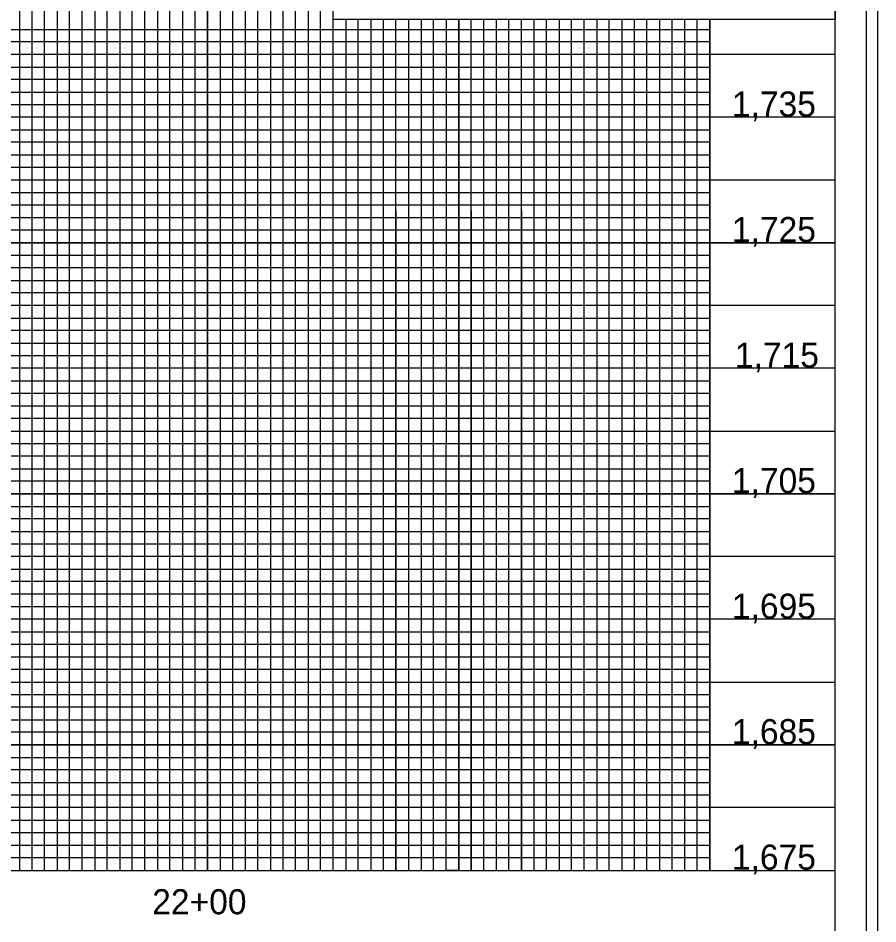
# Model space of a CAD drawing. Extents: x 505692 to 507376, y 438761 to 439861.
# Drawn here: x 507033.2 to 507375.7, y 439314.8 to 439675.6 of the extents above; entities that cross this region are included whole.
import ezdxf

# ---------------------------------------------------------------- set-up
doc = ezdxf.new("R2010")
doc.units = 0
for name, color, linetype in [('Exist Vertical Profile Vertical Axis Label', 7, 'Continuous'), ('Sheet DOT Grid CELL', 7, 'Continuous'), ('Sheet Layout Profile Border Port 1', 7, 'Continuous'), ('Sheet Plot Border Inside CELL', 7, 'Continuous'), ('Sheet Plot Border Outside CELL', 7, 'Continuous'), ('Sheet Profile CELL', 7, 'Continuous'), ('Sheet Profile Grid Major CELL', 7, 'Continuous'), ('Sheet Profile Grid Middle CELL', 7, 'Continuous'), ('Sheet Profile Grid Minor CELL', 7, 'Continuous'), ('Sheet Sticker Exception Certification CELL', 7, 'Continuous')]:
    doc.layers.add(name, color=color, linetype=linetype)

msp = doc.modelspace()

# ---------------------------------------------------------------- linework, layer by layer
at = {"layer": 'Sheet DOT Grid CELL'}
for p, q in [((507058.68, 439336.14), (507058.68, 439836.14)), ((507108.68, 439336.14), (507108.68, 439836.14)), ((507158.68, 439336.14), (507158.68, 439698.59)), ((507208.68, 439336.14), (507208.68, 439675.09)), ((507258.68, 439336.14), (507258.68, 439675.09)), ((507308.68, 439336.14), (507308.68, 439675.09)), ((507358.68, 439636.14), (505858.68, 439636.14)), ((507358.68, 439586.14), (505858.68, 439586.14)), ((507358.68, 439536.14), (505858.68, 439536.14)), ((507358.68, 439486.14), (505858.68, 439486.14)), ((507358.68, 439436.14), (505858.68, 439436.14)), ((507358.68, 439386.14), (505858.68, 439386.14))]:
    msp.add_line(p, q, dxfattribs=at)
at = {"layer": 'Sheet Layout Profile Border Port 1'}
msp.add_lwpolyline([(505908.68, 439836.14), (505908.68, 439336.14), (507108.68, 439336.14), (507108.68, 439486.14), (507108.68, 439636.14), (507108.68, 439836.14)], close=True, dxfattribs=at)
at = {"layer": 'Sheet Plot Border Inside CELL'}
msp.add_lwpolyline([(505704.68, 438783.59), (507371.18, 438783.59), (507371.18, 439838.69), (505704.68, 439838.69)], close=True, dxfattribs=at)
at = {"layer": 'Sheet Plot Border Outside CELL'}
msp.add_lwpolyline([(505691.68, 438761.14), (507375.68, 438761.14), (507375.68, 439861.14), (505691.68, 439861.14)], close=True, dxfattribs=at)
at = {"layer": 'Sheet Profile CELL'}
msp.add_line((505858.68, 439336.14), (507358.68, 439336.14), dxfattribs=at)
msp.add_lwpolyline([(507358.68, 439836.14), (505858.68, 439836.14), (505858.68, 438786.14), (507358.68, 438786.14)], close=True, dxfattribs=at)
at = {"layer": 'Sheet Profile Grid Major CELL'}
for points in [[(507008.68, 439336.14), (507058.68, 439336.14), (507058.68, 439836.14), (507108.68, 439836.14), (507108.68, 439336.14), (507158.68, 439336.14), (507158.68, 439836.14), (507184.98, 439836.14)], [(507308.68, 439675.09), (507308.68, 439336.14), (507358.68, 439336.14), (507358.68, 439686.14)], [(507208.68, 439675.09), (507208.68, 439336.14), (507258.68, 439336.14), (507258.68, 439336.14), (507258.68, 439675.09)], [(507358.68, 439636.14), (505858.68, 439636.14), (505858.68, 439586.14), (507358.68, 439586.14)], [(507358.68, 439536.14), (505858.68, 439536.14), (505858.68, 439486.14), (507358.68, 439486.14)], [(507358.68, 439436.14), (505858.68, 439436.14), (505858.68, 439436.14), (505858.68, 439386.14), (507358.68, 439386.14)]]:
    msp.add_lwpolyline(points, dxfattribs=at)
at = {"layer": 'Sheet Profile Grid Middle CELL'}
for points in [[(506983.68, 439836.14), (507033.68, 439836.14), (507033.68, 439336.14), (507083.68, 439336.14), (507083.68, 439836.14), (507133.68, 439836.14), (507133.68, 439336.14), (507183.68, 439336.14), (507183.68, 439675.09)], [(507183.68, 439598.94), (507183.68, 439336.14), (507233.68, 439336.14), (507233.68, 439675.09)], [(507233.68, 439598.94), (507233.68, 439336.14), (507283.68, 439336.14), (507283.68, 439675.09)], [(507358.68, 439661.14), (505858.68, 439661.14), (505858.68, 439611.14), (507183.68, 439611.14)], [(507183.68, 439611.14), (507358.68, 439611.14)], [(507358.68, 439561.14), (505858.68, 439561.14), (505858.68, 439511.14), (507358.68, 439511.14)], [(507358.68, 439461.14), (505858.68, 439461.14), (505858.68, 439411.14), (507358.68, 439411.14)], [(507358.68, 439361.14), (505858.68, 439361.14)]]:
    msp.add_lwpolyline(points, dxfattribs=at)
at = {"layer": 'Sheet Profile Grid Minor CELL'}
for p, q in [((505908.68, 439671.14), (507308.68, 439671.14)), ((507308.68, 439651.14), (505908.68, 439651.14)), ((505908.68, 439646.14), (507308.68, 439646.14)), ((507308.68, 439626.14), (505908.68, 439626.14)), ((505908.68, 439621.14), (507308.68, 439621.14)), ((507308.68, 439601.14), (505908.68, 439601.14)), ((505908.68, 439596.14), (507308.68, 439596.14)), ((507308.68, 439591.14), (505908.68, 439591.14)), ((505908.68, 439581.14), (507308.68, 439581.14)), ((507308.68, 439576.14), (505908.68, 439576.14)), ((505908.68, 439571.14), (507308.68, 439571.14)), ((507308.68, 439566.14), (505908.68, 439566.14)), ((505908.68, 439556.14), (507308.68, 439556.14)), ((507308.68, 439551.14), (505908.68, 439551.14)), ((505908.68, 439546.14), (507308.68, 439546.14)), ((507308.68, 439541.14), (505908.68, 439541.14)), ((505908.68, 439531.14), (507308.68, 439531.14)), ((507308.68, 439526.14), (505908.68, 439526.14)), ((505908.68, 439521.14), (507308.68, 439521.14)), ((507308.68, 439516.14), (505908.68, 439516.14)), ((505908.68, 439506.14), (507308.68, 439506.14)), ((507308.68, 439501.14), (505908.68, 439501.14)), ((505908.68, 439496.14), (507308.68, 439496.14)), ((507308.68, 439491.14), (505908.68, 439491.14)), ((505908.68, 439481.14), (507308.68, 439481.14)), ((507308.68, 439476.14), (505908.68, 439476.14)), ((505908.68, 439471.14), (507308.68, 439471.14)), ((507308.68, 439466.14), (505908.68, 439466.14)), ((505908.68, 439456.14), (507308.68, 439456.14)), ((507308.68, 439451.14), (505908.68, 439451.14)), ((507308.68, 439446.14), (505908.68, 439446.14)), ((507308.68, 439441.14), (505908.68, 439441.14)), ((505908.68, 439431.14), (507308.68, 439431.14)), ((507308.68, 439426.14), (505908.68, 439426.14)), ((505908.68, 439421.14), (507308.68, 439421.14)), ((507308.68, 439416.14), (505908.68, 439416.14)), ((505908.68, 439406.14), (507308.68, 439406.14)), ((507308.68, 439401.14), (505908.68, 439401.14)), ((505908.68, 439396.14), (507308.68, 439396.14)), ((507308.68, 439391.14), (505908.68, 439391.14)), ((505908.68, 439381.14), (507308.68, 439381.14)), ((507308.68, 439376.14), (505908.68, 439376.14)), ((505908.68, 439371.14), (507308.68, 439371.14)), ((507308.68, 439366.14), (505908.68, 439366.14)), ((505908.68, 439356.14), (507308.68, 439356.14)), ((507308.68, 439351.14), (505908.68, 439351.14)), ((505908.68, 439346.14), (507308.68, 439346.14))]:
    msp.add_line(p, q, dxfattribs=at)
for points in [[(507028.68, 439836.14), (507038.68, 439836.14), (507038.68, 439336.14), (507043.68, 439336.14), (507043.68, 439836.14), (507048.68, 439836.14), (507048.68, 439336.14)], [(507048.68, 439336.14), (507053.68, 439336.14), (507053.68, 439836.14)], [(507063.68, 439836.14), (507063.68, 439336.14), (507068.68, 439336.14), (507068.68, 439836.14)], [(507073.68, 439836.14), (507073.68, 439336.14), (507078.68, 439336.14), (507078.68, 439836.14)], [(507088.68, 439836.14), (507088.68, 439336.14), (507093.68, 439336.14), (507093.68, 439836.14)], [(507098.68, 439836.14), (507098.68, 439336.14), (507103.68, 439336.14), (507103.68, 439836.14)], [(507113.68, 439836.14), (507113.68, 439336.14), (507118.68, 439336.14), (507118.68, 439836.14)], [(507123.68, 439836.14), (507123.68, 439336.14), (507128.68, 439336.14), (507128.68, 439836.14)], [(507138.68, 439836.14), (507138.68, 439336.14), (507143.68, 439336.14), (507143.68, 439836.14)], [(507148.68, 439836.14), (507148.68, 439336.14), (507153.68, 439336.14), (507153.68, 439836.14)], [(507163.68, 439675.09), (507163.68, 439336.14), (507168.68, 439336.14), (507168.68, 439675.09)], [(507173.68, 439675.09), (507173.68, 439336.14), (507178.68, 439336.14), (507178.68, 439675.09)], [(507188.68, 439675.09), (507188.68, 439336.14), (507188.68, 439336.14), (507193.68, 439336.14), (507198.68, 439336.14), (507198.68, 439675.09)], [(507193.68, 439675.09), (507193.68, 439336.14)], [(507203.67, 439675.09), (507203.58, 439336.19), (507208.58, 439336.19), (507213.68, 439336.14), (507213.68, 439675.09)], [(507213.68, 439598.94), (507213.68, 439336.14), (507218.68, 439336.14), (507218.68, 439675.09)], [(507223.68, 439675.09), (507223.68, 439336.14), (507228.68, 439336.14), (507228.68, 439675.09)], [(507238.68, 439675.09), (507238.68, 439336.14), (507243.68, 439336.14), (507243.68, 439675.09)], [(507248.68, 439675.09), (507248.68, 439336.14), (507253.68, 439336.14), (507253.68, 439675.09)], [(507263.68, 439675.09), (507263.68, 439336.14), (507268.68, 439336.14), (507268.68, 439675.09)], [(507273.68, 439675.09), (507273.68, 439336.14), (507278.68, 439336.14), (507278.68, 439675.09)], [(507288.68, 439675.09), (507288.68, 439336.14), (507293.68, 439336.14), (507293.68, 439675.09)], [(507298.68, 439675.09), (507298.68, 439336.14), (507303.68, 439336.14), (507303.68, 439675.09)], [(507308.68, 439666.14), (505908.68, 439666.14), (505908.68, 439656.14), (507308.68, 439656.14)], [(507308.68, 439641.14), (505908.68, 439641.14), (505908.68, 439631.14), (507308.68, 439631.14)], [(507308.68, 439616.14), (505908.68, 439616.14), (505908.68, 439606.14), (507308.68, 439606.14)], [(507308.68, 439341.14), (505908.68, 439341.14)]]:
    msp.add_lwpolyline(points, dxfattribs=at)
at = {"layer": 'Sheet Sticker Exception Certification CELL'}
for p, q in [((507158.63, 439675.09), (507158.63, 439698.59)), ((507158.63, 439675.09), (507158.63, 439698.59)), ((507358.67, 439698.58), (507358.67, 439675.08)), ((507358.67, 439698.58), (507358.67, 439675.08)), ((507358.67, 439675.09), (507158.63, 439675.09)), ((507358.67, 439675.09), (507158.63, 439675.09))]:
    msp.add_line(p, q, dxfattribs=at)

# ---------------------------------------------------------------- texts
at = {"layer": 'Exist Vertical Profile Vertical Axis Label'}
for s, p in [('1,735', (507317.53, 439636.39)), ('1,725', (507317.53, 439586.39)), ('1,715', (507318.73, 439536.39)), ('1,705', (507317.53, 439486.39)), ('1,695', (507317.53, 439436.39)), ('1,685', (507317.53, 439386.39)), ('1,675', (507317.53, 439336.39)), ('22+00', (507086.61, 439318.64))]:
    msp.add_text(s, height=10, dxfattribs=at).set_placement(p)

doc.saveas('drawing.dxf')
